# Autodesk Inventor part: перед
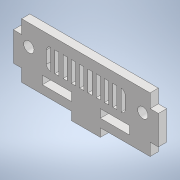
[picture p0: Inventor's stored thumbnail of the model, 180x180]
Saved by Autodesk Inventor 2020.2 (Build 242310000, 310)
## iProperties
Created: 2020-04
Part Number: перед
Material: Типовые
Document SubType Name: Modeling
Designer: Алексей
Density: 1 g/cm^3
Appearance: По умолчанию
Author: Алексей
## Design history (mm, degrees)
sketch "Эскиз1"
  geometry: L1 (70, 14)-(70, 0) reference; L2 (66, 14)-(70, 14) reference; L3 (66, 0)-(66, 14) reference; L4 (66, 0)-(70, 0) reference; L5 (4, 14)-(4, 0) reference; L6 (0, 14)-(4, 14) reference; L7 (0, 0)-(0, 14) reference; L8 (0, 0)-(4, 0) reference; L9 (66, 20.586)-(70, 20.586) reference; L10 (0, 20.586)-(4, 20.586) reference; L11 (66, -6)-(42, -6) reference; L12 (4, 20.586)-(66, 20.586); L13 (66, 20.586)-(66, -6); L14 (66, -6)-(4, -6); L15 (4, -6)-(4, 20.586); L16 (28, -6)-(42, -6) reference; L17 (28, -10)-(28, -6) reference; L18 (42, -10)-(28, -10) reference; L19 (42, -10)-(42, -6) reference; 7 further points
  constraints: 8 end point, 2 parallel, 1 horizontal, 1 perpendicular
extrude "Выдавливание1" new body sketch "Эскиз1" distance "d0" = 4; taper "d1" = 0 deg
sketch "Эскиз2"
  geometry: L1 (14, -2)-(28, -2); L2 (28, -2)-(28, 2); L3 (28, 2)-(14, 2); L4 (14, 2)-(14, -2); L5 (42, -2)-(56, -2); L6 (56, -2)-(56, 2); L7 (56, 2)-(42, 2); L8 (42, 2)-(42, -2); L9 (4, -6)-(28, -6) reference; L10 (28, -6)-(28, -10) reference; L11 (42, -10)-(42, -6) reference; 1 further point
  constraints: 16 end point, 4 parallel, 2 collinear, 2 horizontal, 2 perpendicular, 1 point on line
  dimensions: "d2" = 14 distance of L2.end L3.end; "d3" = 14 distance of L6.end L7.end; "d4" = 4 distance of L7.end L5.start; "d5" = 4 distance of L1.end L2.end; "d6" = 4 distance between parallel lines of L9 L1
extrude "Выдавливание2" cut sketch "Эскиз2" extent not by distance; stored distance "d7" = 0; taper "d8" = 0 deg
sketch "Эскиз3" dims "d14" = 10
  geometry: L1 (16, 15.586)-(18, 15.586); L2 (18, 15.586)-(18, 5.586); L3 (18, 5.586)-(16, 5.586); L4 (16, 5.586)-(16, 15.586); L5 (66, 20.586)-(4, 20.586) reference; L6 (20, 5.586)-(20, 15.586); L7 (20, 15.586)-(22, 15.586); L8 (22, 15.586)-(22, 5.586); L9 (22, 5.586)-(20, 5.586); L10 (24, 5.586)-(24, 15.586); L11 (24, 15.586)-(26, 15.586); L12 (26, 15.586)-(26, 5.586); L13 (26, 5.586)-(24, 5.586); L14 (28, 5.586)-(28, 15.586); L15 (28, 15.586)-(30, 15.586); L16 (30, 15.586)-(30, 5.586); L17 (30, 5.586)-(28, 5.586); L18 (32, 5.586)-(32, 15.586); L19 (32, 15.586)-(34, 15.586); L20 (34, 15.586)-(34, 5.586); L21 (34, 5.586)-(32, 5.586); L22 (36, 5.586)-(36, 15.586); L23 (36, 15.586)-(38, 15.586); L24 (38, 15.586)-(38, 5.586); L25 (38, 5.586)-(36, 5.586); L26 (40, 5.586)-(40, 15.586); L27 (40, 15.586)-(42, 15.586); L28 (42, 15.586)-(42, 5.586); L29 (42, 5.586)-(40, 5.586); L30 (44, 5.586)-(44, 15.586); L31 (44, 15.586)-(46, 15.586); L32 (46, 15.586)-(46, 5.586); L33 (46, 5.586)-(44, 5.586); L34 (48, 5.586)-(48, 15.586); L35 (48, 15.586)-(50, 15.586); L36 (50, 15.586)-(50, 5.586); L37 (50, 5.586)-(48, 5.586); L38 (52, 5.586)-(52, 15.586); L39 (52, 15.586)-(54, 15.586); L40 (54, 15.586)-(54, 5.586); L41 (54, 5.586)-(52, 5.586); L42 (4, 20.586)-(4, 14) reference; L43 (16, 15.586)-(4, 15.586); L44 (54, 15.586)-(66, 15.586); 3 further points; 1 other entity
  constraints: 84 end point, 2 horizontal, 2 parallel, 2 perpendicular, 2 point on line, 1 collinear, 74 other
  dimensions: "d9" = 2 distance of L2.end L3.end; "d10" = 10 distance of L1.end L2.end; "d11" = 5 distance between parallel lines of L5 L1; "d17" = 4 distance of L3.end L6.start
extrude "Выдавливание3" cut sketch "Эскиз3" extent not by distance; stored distance "d21" = 0; taper "d22" = 0 deg
fillet "Сопряжение1" dims "d23" = 2
sketch "Эскиз4"
  geometry: L1 (52, 5.586)-(52, 15.586) reference; L2 (18, 15.586)-(18, 5.586) reference; L3 (0, 14)-(0, 0) reference; L4 (70, 0)-(70, 14) reference; C1 r 2.5 at (7.5, 10.586); C2 r 2.5 at (62.5, 10.586); 2 further points
  constraints: 2 centre point, 2 horizontal alignment, 2 midpoint
  dimensions: "d24" = 5 diameter of C1; "d25" = 5 diameter of C2; "d30" = 7.5 distance from line of L3 C1.centre; "d31" = 7.5 distance from line of L4 C2.centre
extrude "Выдавливание4" cut sketch "Эскиз4" extent not by distance; stored distance "d28" = 0; taper "d29" = 0 deg
node "Твердое тело1"
node "Ссылка1"
node "Ссылка2"
node "Ссылка3"
node "Ссылка4"
node "Ссылка5"
node "Ссылка6"
feature "Машинка.iam"
